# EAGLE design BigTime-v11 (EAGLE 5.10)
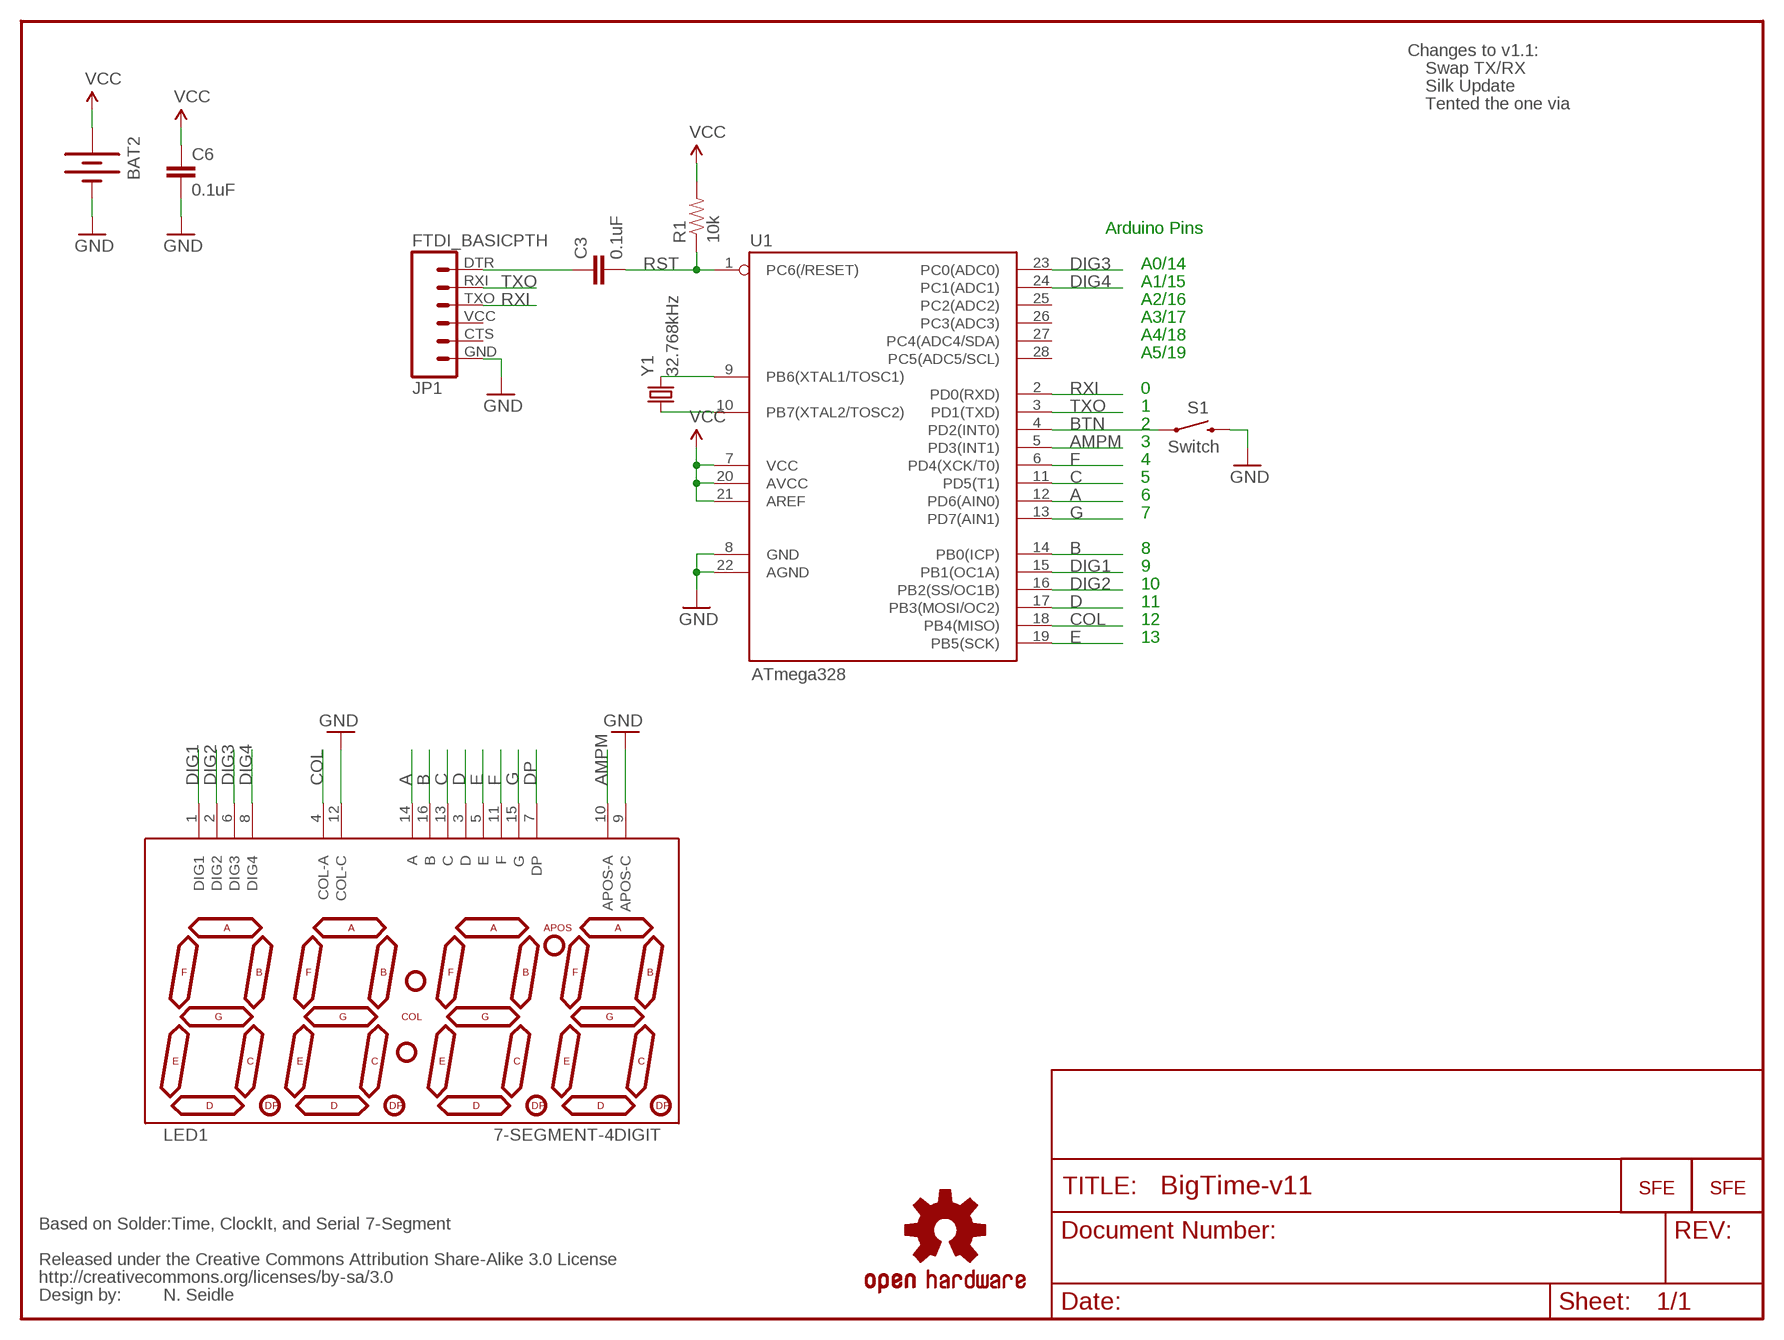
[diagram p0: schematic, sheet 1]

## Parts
BAT2  BATTERYBATTCON_20MM_4LEGS  [BATTCON_20MM_4LEGS]
C3  0.1uF  CAPPTH2  [CAP-PTH-SMALL2]
C6  0.1uF  CAPPTH2  [CAP-PTH-SMALL2]
JP1  FTDI_BASICPTH  [FTDI_BASIC]
LED1  7-SEGMENT-4DIGIT  7-SEGMENT-4DIGIT-YOUNGSUN  [7-SEGMENT-4DIGIT-YOUNGSUN]
R1  10k  RESISTORAXIAL-0.3  [AXIAL-0.3]
S1  Switch  SWITCH-MOMENTARY-2PTH-SIDE  [TACTILE-PTH-SIDE]
U1  ATmega328  AVR-MEGA8-PSIM  [DIL28-3-SIMON]
U$1  LOGO-SFESK  [SFE-LOGO-FLAME]
U$2  CREATIVE_COMMONS  [CREATIVE_COMMONS]
U$4  OSHW-LOGOS  [OSHW-LOGO-S]
U$5  LOGO-SFENW2  [SFE-NEW-WEB]
Y1  32.768kHz  CRYSTALTC26H  [TC26H]

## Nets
A: LED1.14(A) U1.12(PD6(AIN0))
AMPM: LED1.10(APOS-A) U1.5(PD3(INT1))
B: LED1.16(B) U1.14(PB0(ICP))
BTN: S1.1 U1.4(PD2(INT0))
C: LED1.13(C) U1.11(PD5(T1))
COL: LED1.4(COL-A) U1.18(PB4(MISO))
D: LED1.3(D) U1.17(PB3(MOSI/OC2))
DIG1: LED1.1(DIG1) U1.15(PB1(OC1A))
DIG2: LED1.2(DIG2) U1.16(PB2(SS/OC1B))
DIG3: LED1.6(DIG3) U1.23(PC0(ADC0))
DIG4: LED1.8(DIG4) U1.24(PC1(ADC1))
DP: LED1.7(DP)
E: LED1.5(E) U1.19(PB5(SCK))
F: LED1.11(F) U1.6(PD4(XCK/T0))
G: LED1.15(G) U1.13(PD7(AIN1))
GND: BAT2.2(-) C6.2 JP1.GND LED1.9(APOS-C) LED1.12(COL-C) S1.2 U1.8(GND) U1.22(AGND)
N$1: U1.9(PB6(XTAL1/TOSC1)) Y1.2
N$2: U1.10(PB7(XTAL2/TOSC2)) Y1.1
N$3: C3.1 JP1.DTR
RST: C3.2 R1.P$1 U1.1(PC6(/RESET))
RXI: JP1.TXO U1.2(PD0(RXD))
TXO: JP1.RXI U1.3(PD1(TXD))
VCC: BAT2.3(+) C6.1 R1.P$2 U1.7(VCC) U1.20(AVCC) U1.21(AREF)
Unconnected: JP1.CTS JP1.VCC U1.25(PC2(ADC2)) U1.26(PC3(ADC3)) U1.27(PC4(ADC4/SDA)) U1.28(PC5(ADC5/SCL))

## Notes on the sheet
- Changes to v1.1:
- Swap TX/RX
- Silk Update
- Tented the one via
- Arduino Pins
- A0/14
- A1/15
- A2/16
- A3/17
- A4/18
- A5/19
- 0
- 1
- 2
- 3
- 4
- 5
- 6
- 7
- 8
- 9
- 10
- 11
- 12
- 13
- Based on Solder:Time, ClockIt, and Serial 7-Segment
- N. Seidle

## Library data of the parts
BAT2 = Testing:BATTERY: Battery Holders
C3 C6 = SparkFun:CAP: Capacitor
JP1 = SparkFun:FTDI_BASIC: FTDI Basic: 3.3V and 5V
LED1 = SparkFun:7-SEGMENT-4DIGIT-YOUNGSUN: This is a part for the 4-Digit 7-segment LEDs from Young Sun. Different from the Digikey LEDs, all 16 pins are used. The LONGPADS Variant is used for a test jig, but you may like it because there is more pad to solder to. If you are concerned about routing space, the standard works just fine though.
R1 = SparkFun:RESISTOR: Resistor
S1 = SparkFun:SWITCH-MOMENTARY-2
U1 = SparkFun:AVR-MEGA8-P: MICROCONTROLLER 8 Kbytes FLASH 1 kbytes SRAM 512 bytes EEPROM USART 4-channel 10 bit ADC 2-channel 8 bit ADC
U$1 U$5 = SparkFun:LOGO-SFE: Spark Fun Electronics PCB Logo
U$2 = SparkFun:CREATIVE_COMMONS
U$4 = SparkFun:OSHW-LOGO: Open Source Hardware Logo This logo indicates the piece of hardware it is found on incorporates a OSHW license and/or adheres to the definition of open source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
Y1 = SparkFun:CRYSTAL: Crystals

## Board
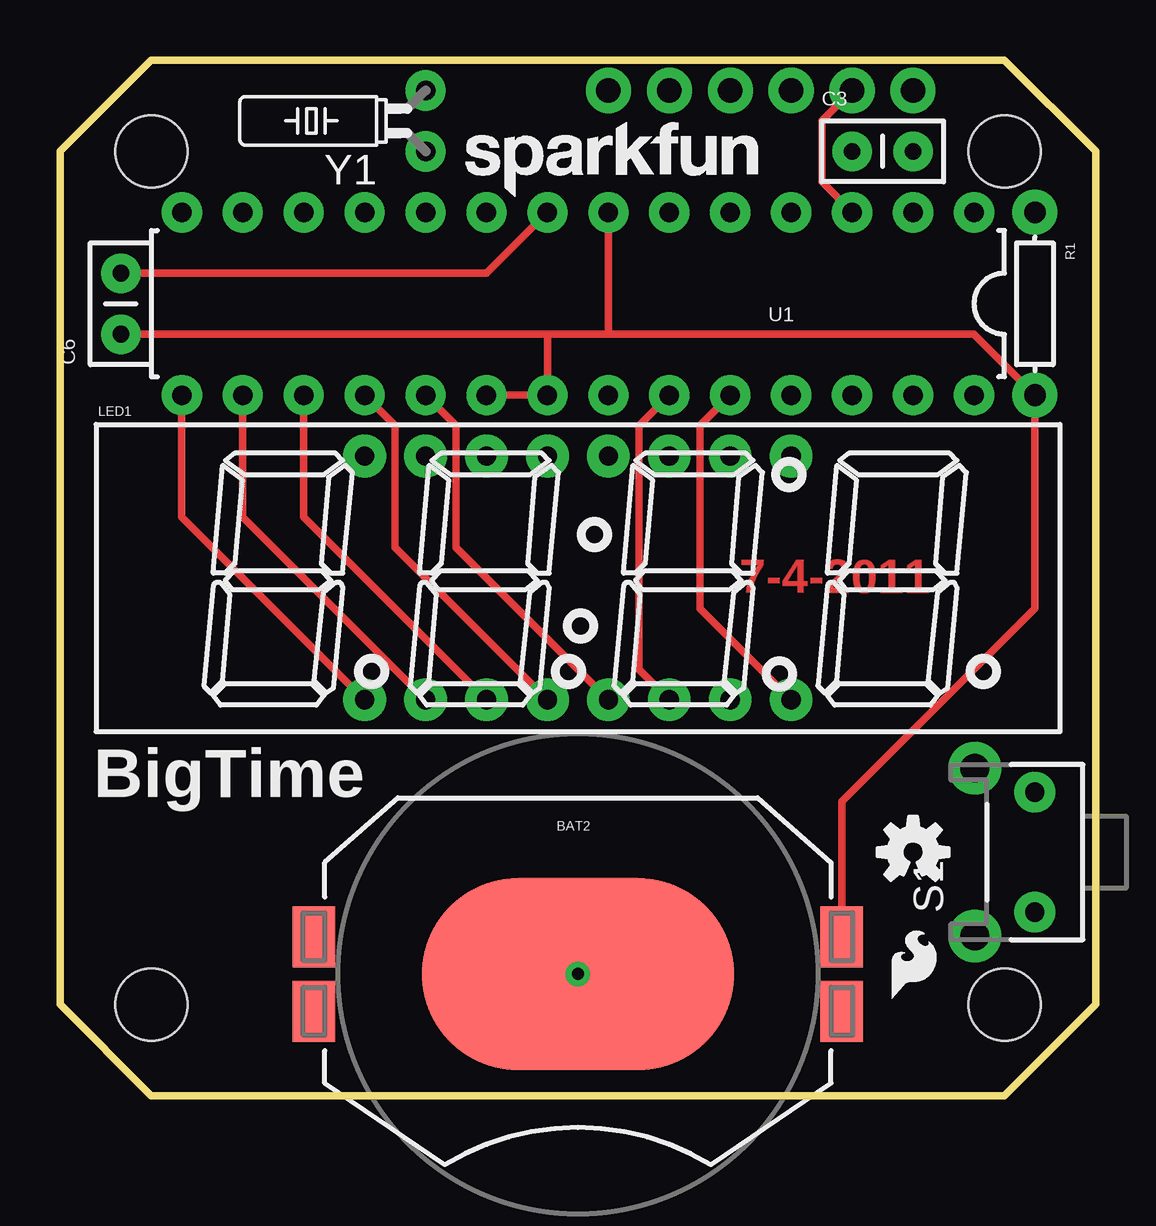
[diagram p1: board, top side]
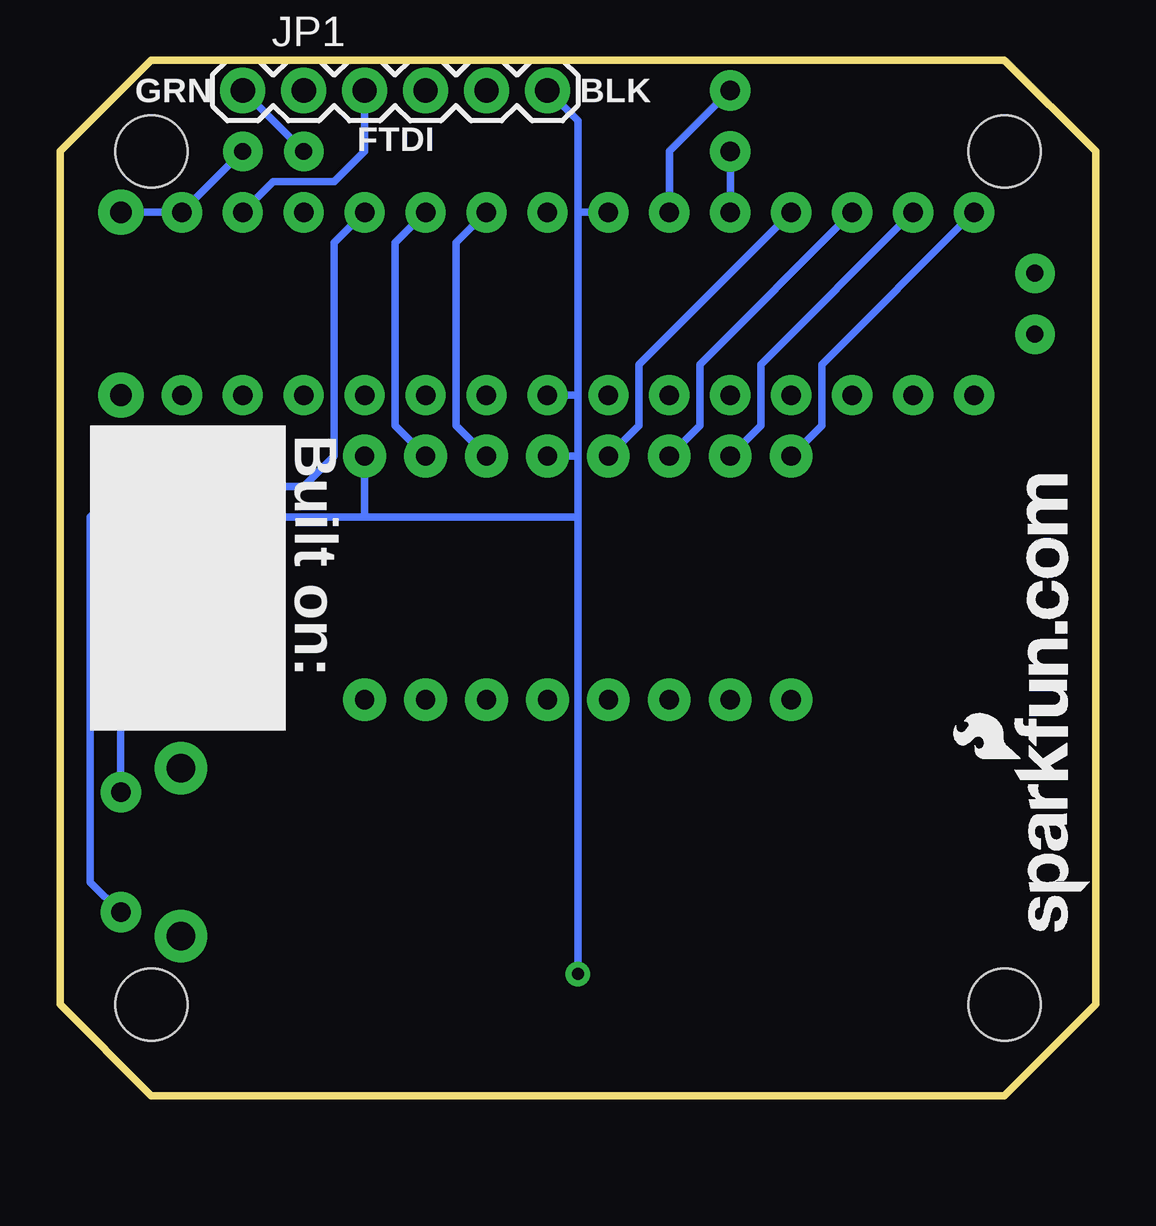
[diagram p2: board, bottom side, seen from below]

Size 43.18 x 43.18 mm. Coordinates in mm from the lower left corner, seen from the top.
Outline: 0,39.37 0,3.81 3.81,0 39.37,0 43.18,3.81 43.18,39.37 39.37,43.18 3.81,43.18 0,39.37
Copper layers (1*16): Top 0.035mm / dielectric 1.5mm / Bottom 0.035mm
Design rules "SparkFun": minimum track width 8mil, minimum drill 20mil, track to track 8mil, track to pad 8mil, pad to pad 8mil, via to via 8mil, smd to smd 8mil, copper to edge 10mil, drill to drill 8mil, minimum pad ring 12mil, minimum via ring 10mil, stop-mask expansion 4mil, vias tented up to drill 25mil, thermal gap 10mil
Holes 3 mm at 3.81,39.37 39.37,3.81 39.37,39.37 3.81,3.81

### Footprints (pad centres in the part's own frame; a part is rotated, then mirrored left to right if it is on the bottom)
BATTCON_20MM_4LEGS = smd 1.778 x 2.54: 1 -11,1.55; 3 11,1.55; P$1 -11,-1.55; P$2 11,-1.55 | smd 13 x 8: 2 0,0
CAP-PTH-SMALL2 = drill 0.7 pad 1.651 round: 1 0,0; 2 2.54,0
FTDI_BASIC = drill 1.016 pad 1.88 round: CTS 10.16,0; DTR 0,0; GND 12.7,0; RXI 2.54,0; TXO 5.08,0; VCC 7.62,0
7-SEGMENT-4DIGIT-YOUNGSUN = drill 0.8 pad 1.778 round: 1 -8.89,-5.08; 2 -6.35,-5.08; 3 -3.81,-5.08; 4 -1.27,-5.08; 5 1.27,-5.08; 6 3.81,-5.08; 7 6.35,-5.08; 8 8.89,-5.08; 9 8.89,5.08; 10 6.35,5.08; 11 3.81,5.08; 12 1.27,5.08; 13 -1.27,5.08; 14 -3.81,5.08; 15 -6.35,5.08; 16 -8.89,5.08
AXIAL-0.3 = drill 0.9 pad 1.88 round: P$1 -3.81,0; P$2 3.81,0
TACTILE-PTH-SIDE = drill 0.8 pad 1.7 round: 1 -2.5,0; 2 2.5,0 | drill 1.2 pad 2.2 round: ANCHOR1 -3.5,2.5; ANCHOR2 3.5,2.5
DIL28-3-SIMON = drill 0.813 pad 1.676 round: 1 -16.51,-3.81; 2 -13.97,-3.81; 3 -11.43,-3.81; 4 -8.89,-3.81; 5 -6.35,-3.81; 6 -3.81,-3.81; 7 -1.27,-3.81; 8 1.27,-3.81; 9 3.81,-3.81; 10 6.35,-3.81; 11 8.89,-3.81; 12 11.43,-3.81; 13 13.97,-3.81; 14 16.51,-3.81; 15 16.51,3.81; 16 13.97,3.81; 17 11.43,3.81; 18 8.89,3.81; 19 6.35,3.81; 20 3.81,3.81; 21 1.27,3.81; 22 -1.27,3.81; 23 -3.81,3.81; 24 -6.35,3.81; 25 -8.89,3.81; 26 -11.43,3.81; 27 -13.97,3.81; 28 -16.51,3.81
TC26H = drill 0.813 pad 1.676 round: 1 -1.27,0; 2 1.27,0

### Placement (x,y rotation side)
BAT2  21.59,5.08 0 top
C3  33.02,39.37 0 top
C6  2.54,31.75 90 top
JP1  35.56,41.91 0 bottom
LED1  21.59,21.59 0 top
R1  40.64,33.02 270 top
S1  40.64,10.16 90 top
U1  21.59,33.02 180 top
U$1  34.67,4.06 0 top
U$2  not placed on the board
U$3  LOGO-SFENEW  [SFE-NEW-WEBLOGO]  0.25,6.86 90 bottom
U$4  35.56,10.16 0 top
U$5  16.89,37.47 0 top
Y1  15.24,40.64 90 top

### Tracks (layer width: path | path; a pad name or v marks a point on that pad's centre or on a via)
A
  Bottom 0.305: U1.12 16.51,30.48 16.51,27.94 LED1.14
AMPM
  Bottom 0.305: U1.5 29.21,35.56 29.21,27.94 LED1.10
B
  Bottom 0.305: U1.14 11.43,30.48 11.43,27.94 LED1.16
BTN
  Bottom 0.305: U1.4 31.75,35.56 31.75,26.67 33.02,25.4 40.64,25.4 41.91,24.13 41.91,8.89 40.68,7.66 S1.1
C
  Bottom 0.305: U1.11 19.05,30.48 19.05,27.94 LED1.13
COL
  Top 0.305: U1.18 13.97,27.94 13.97,22.86 LED1.4
D
  Top 0.305: LED1.3 10.16,24.13 U1.17
DIG1
  Top 0.305: LED1.1 5.08,24.13 U1.15
DIG2
  Top 0.305: LED1.2 7.62,24.13 U1.16
DIG3
  Top 0.305: U1.23 24.13,27.94 24.13,17.78 LED1.6
DIG4
  Top 0.305: U1.24 26.67,27.94 26.67,20.32 LED1.8
E
  Top 0.305: U1.19 16.51,27.94 16.51,22.86 LED1.5
F
  Bottom 0.305: U1.6 26.67,35.56 26.67,27.94 LED1.11
G
  Bottom 0.305: U1.13 13.97,30.48 13.97,27.94 LED1.15
GND  (via drill 0.51)
  Top 0.305: C6.2 17.78,34.29 U1.8
  Bottom 0.305: BAT2.2 21.59,24.13 | 21.59,24.13 21.59,26.67 | 21.59,26.67 21.59,29.21 | 21.59,29.21 U1.22 | 21.59,26.67 LED1.12 | 21.59,24.13 30.48,24.13 | 30.48,24.13 LED1.9 | S1.2 40.64,22.86 39.37,24.13 30.48,24.13 | 21.59,29.21 21.59,36.83 | 21.59,36.83 21.59,40.64 JP1.GND | 21.59,36.83 U1.8
  other vias: 21.59,5.08
N$1
  Bottom 0.305: Y1.2 17.78,39.37 U1.9
N$2
  Bottom 0.305: U1.10 Y1.1
N$3
  Bottom 0.305: C3.1 JP1.DTR
RST
  Bottom 0.305: C3.2 U1.1 R1.P$1
RXI
  Bottom 0.305: U1.2 34.29,38.1 31.75,38.1 30.48,39.37 JP1.TXO
TXO
  Top 0.305: U1.3 31.75,38.1 31.75,40.64 JP1.RXI
VCC
  Top 0.305: 22.86,31.75 U1.7 | 22.86,31.75 38.1,31.75 R1.P$2 40.64,20.32 32.59,12.27 BAT2.3 | 20.32,31.75 22.86,31.75 | C6.1 20.32,31.75 | 20.32,31.75 U1.21 U1.20

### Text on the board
Top: 7-4-2011
tPlace: BigTime | N. Seidle
bPlace: BLK | GRN | FTDI | Built on:
